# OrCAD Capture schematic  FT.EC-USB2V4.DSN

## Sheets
1 INDEX: title: 01- INDEX; rev: 1.0; note: 17 HaYetsira Street; note: Yokneam Illit, Israel 2069208
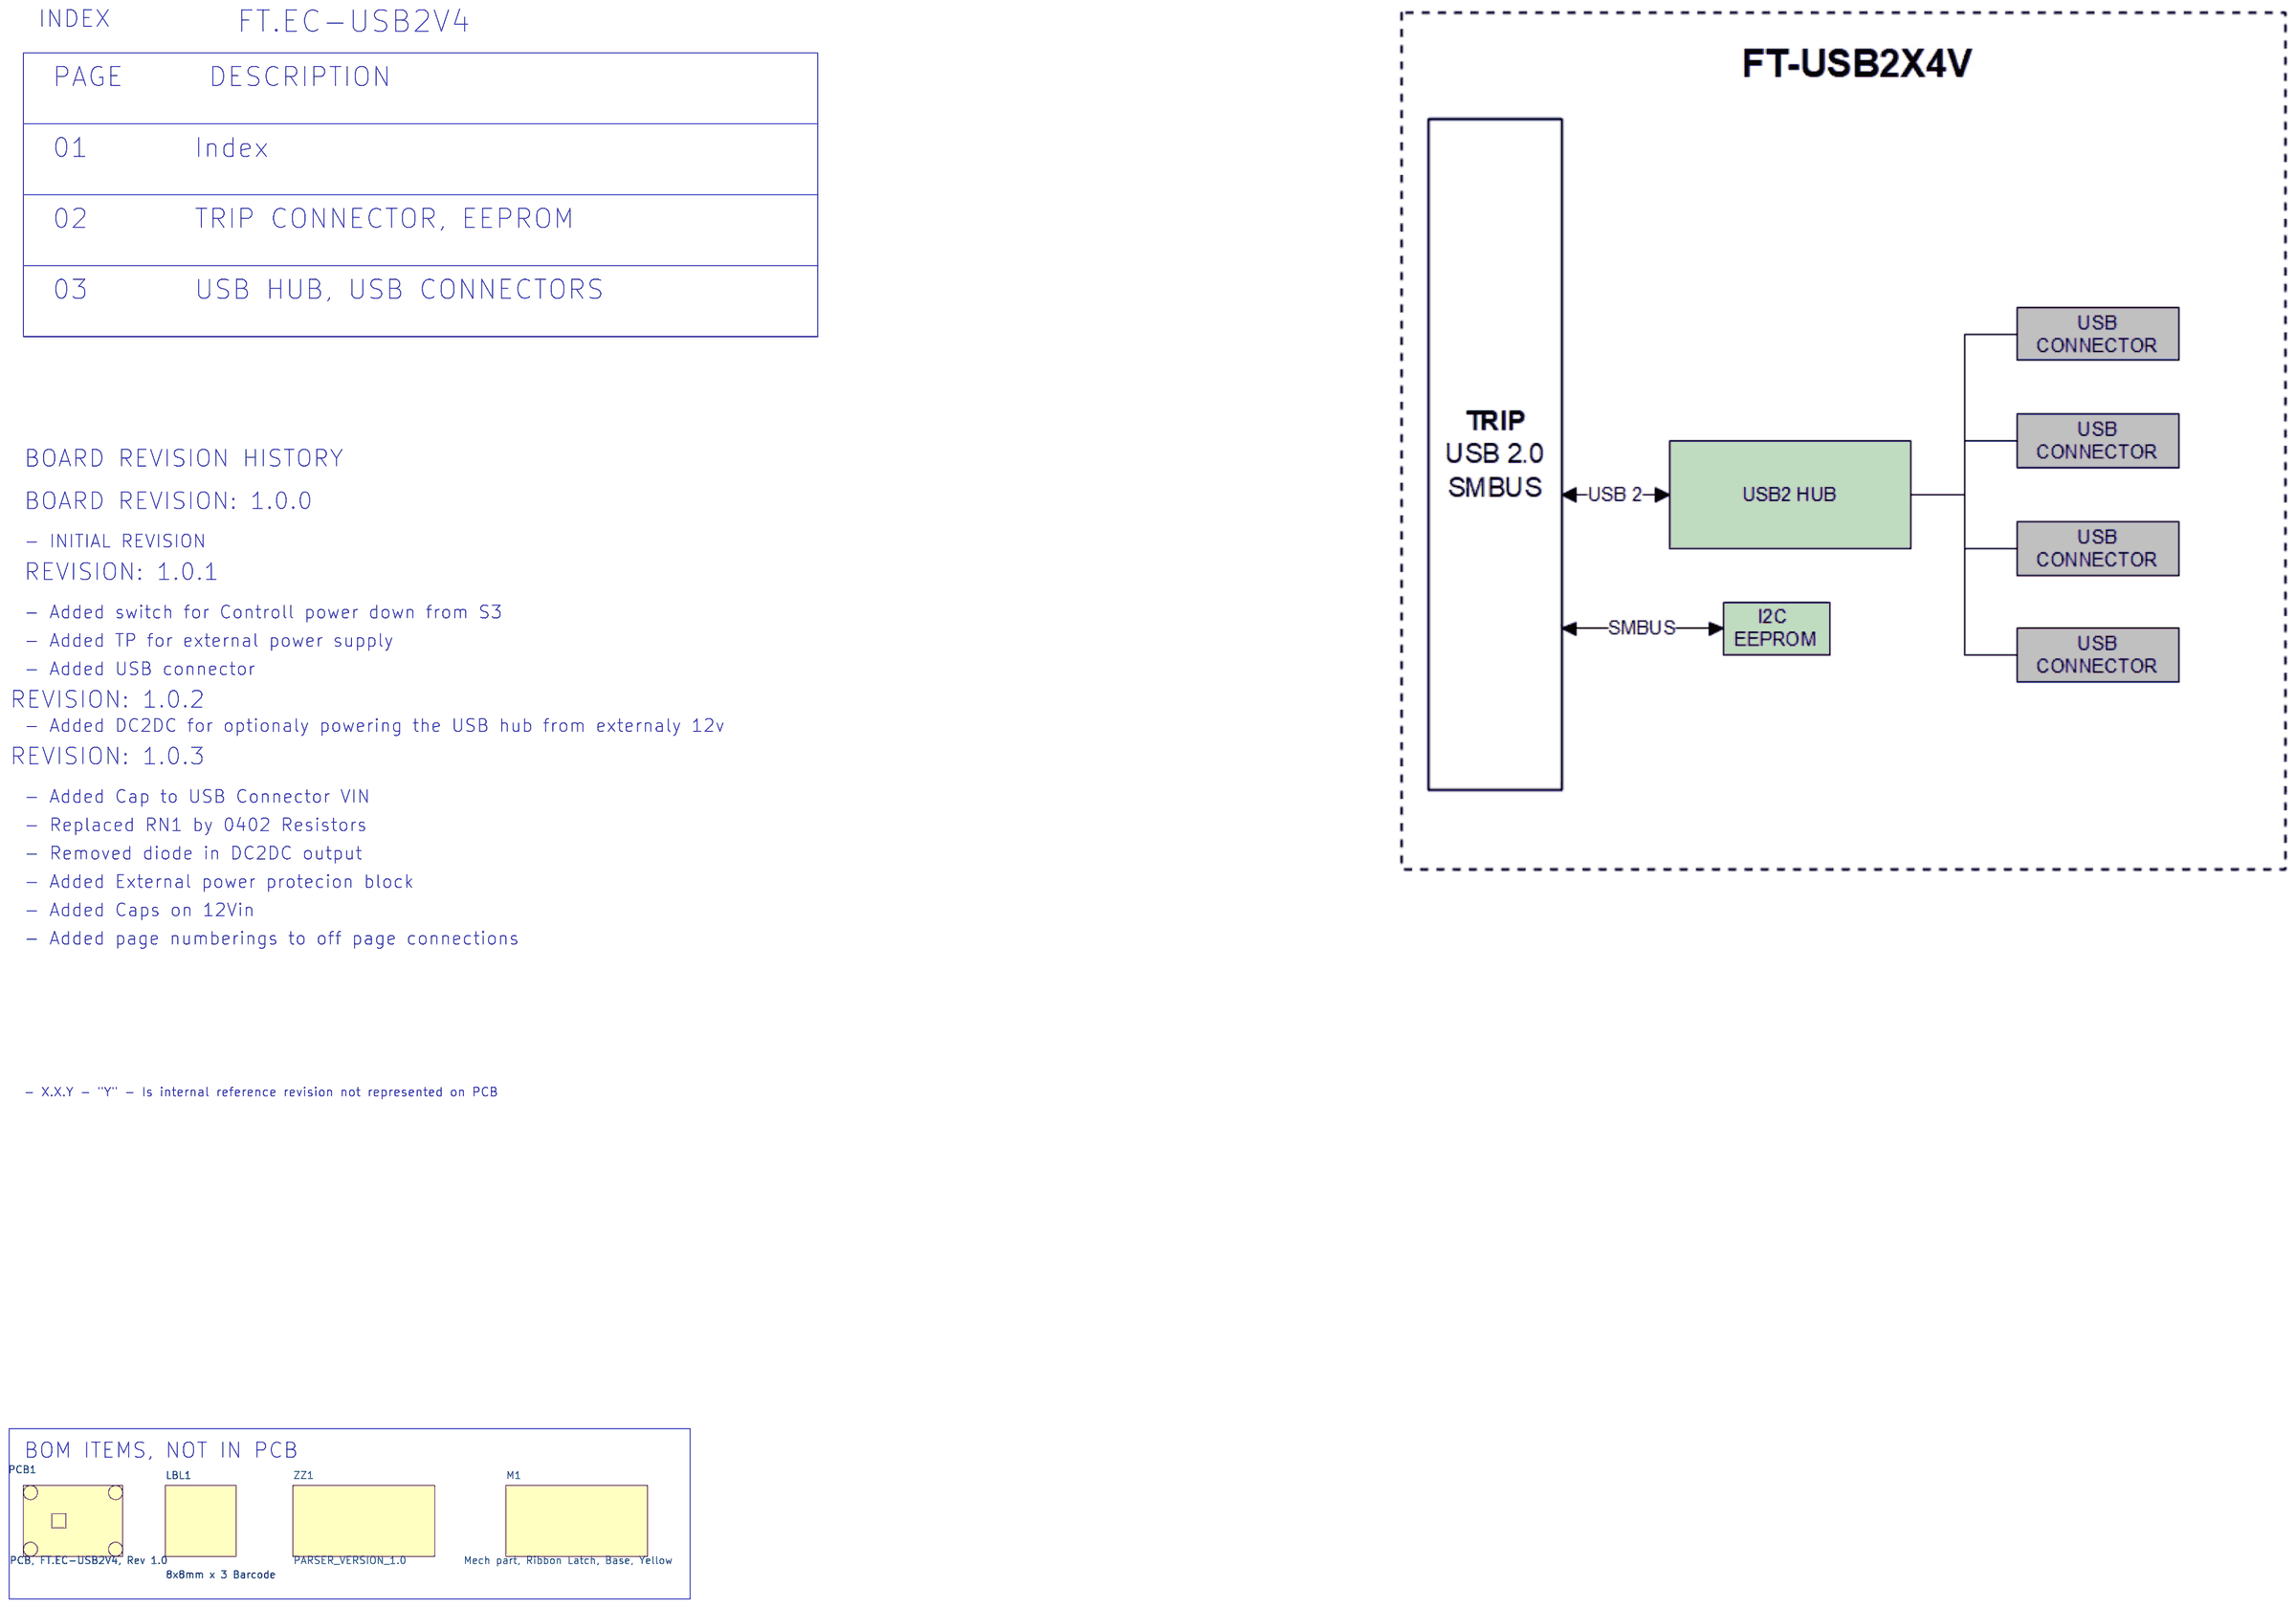
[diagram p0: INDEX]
2 CONN: size A3; title: 02- connector
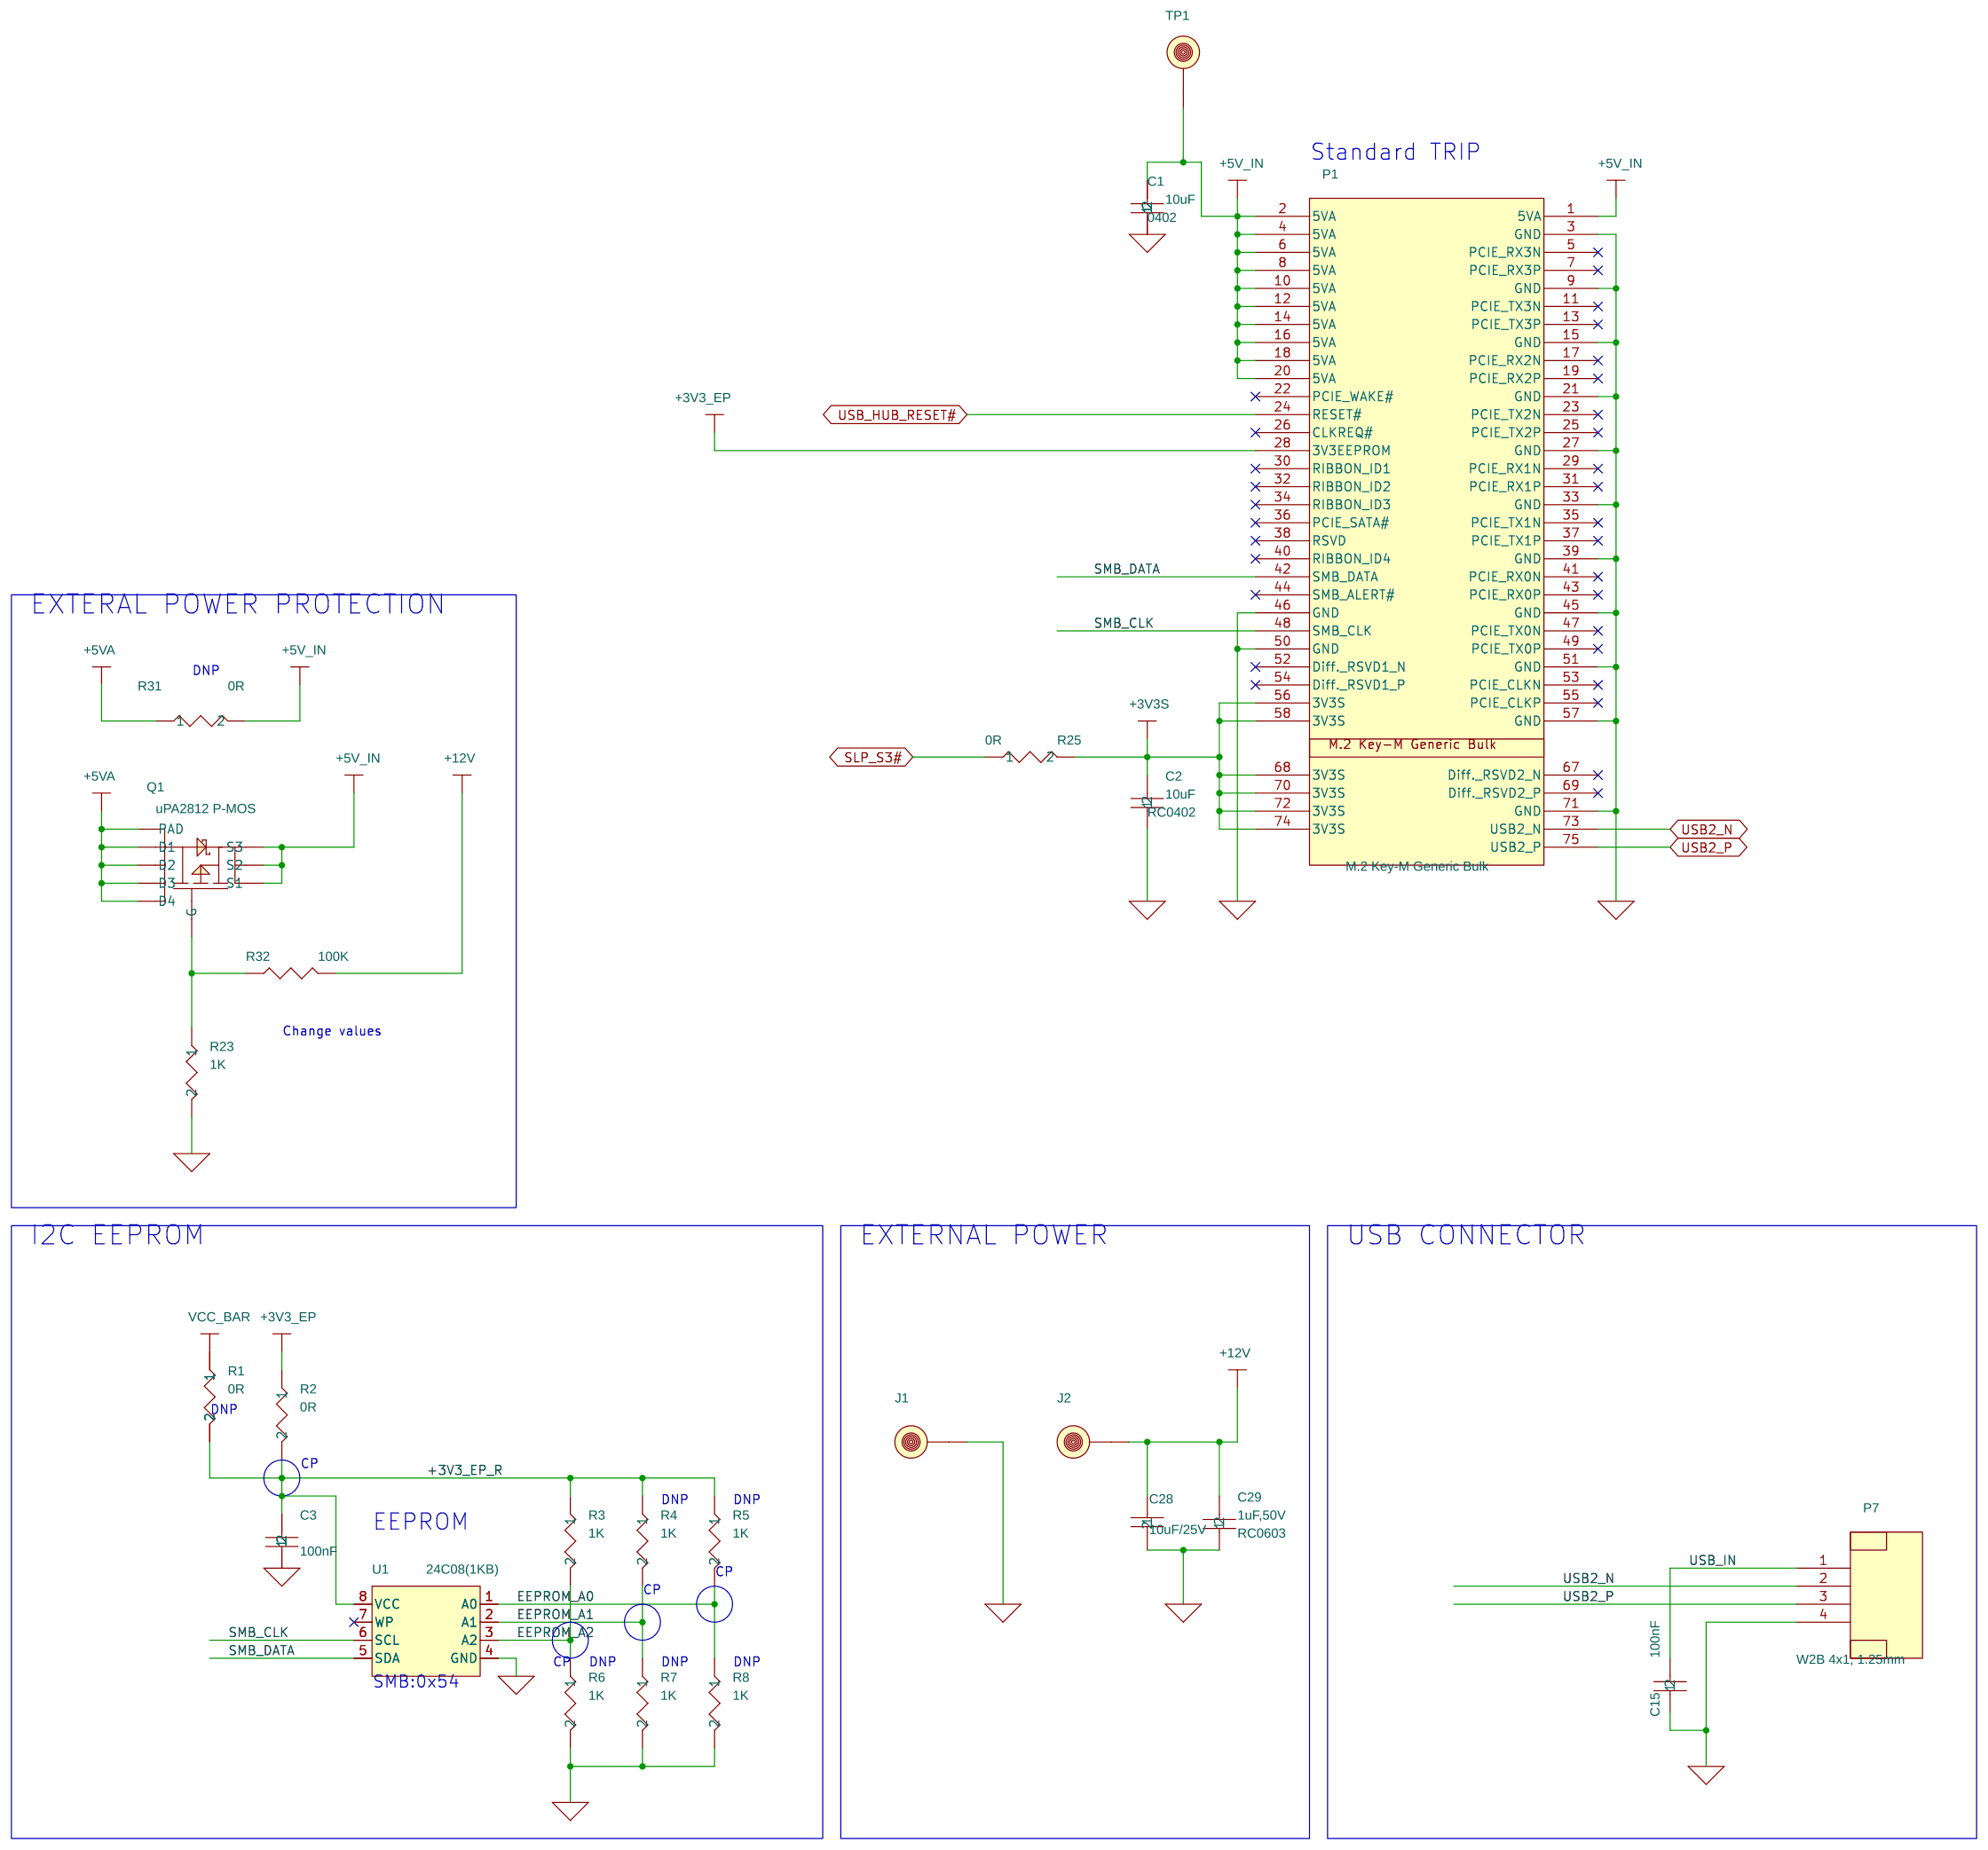
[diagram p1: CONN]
3 HUB, CONN: size A3; title: 03- HUB, USB CONN
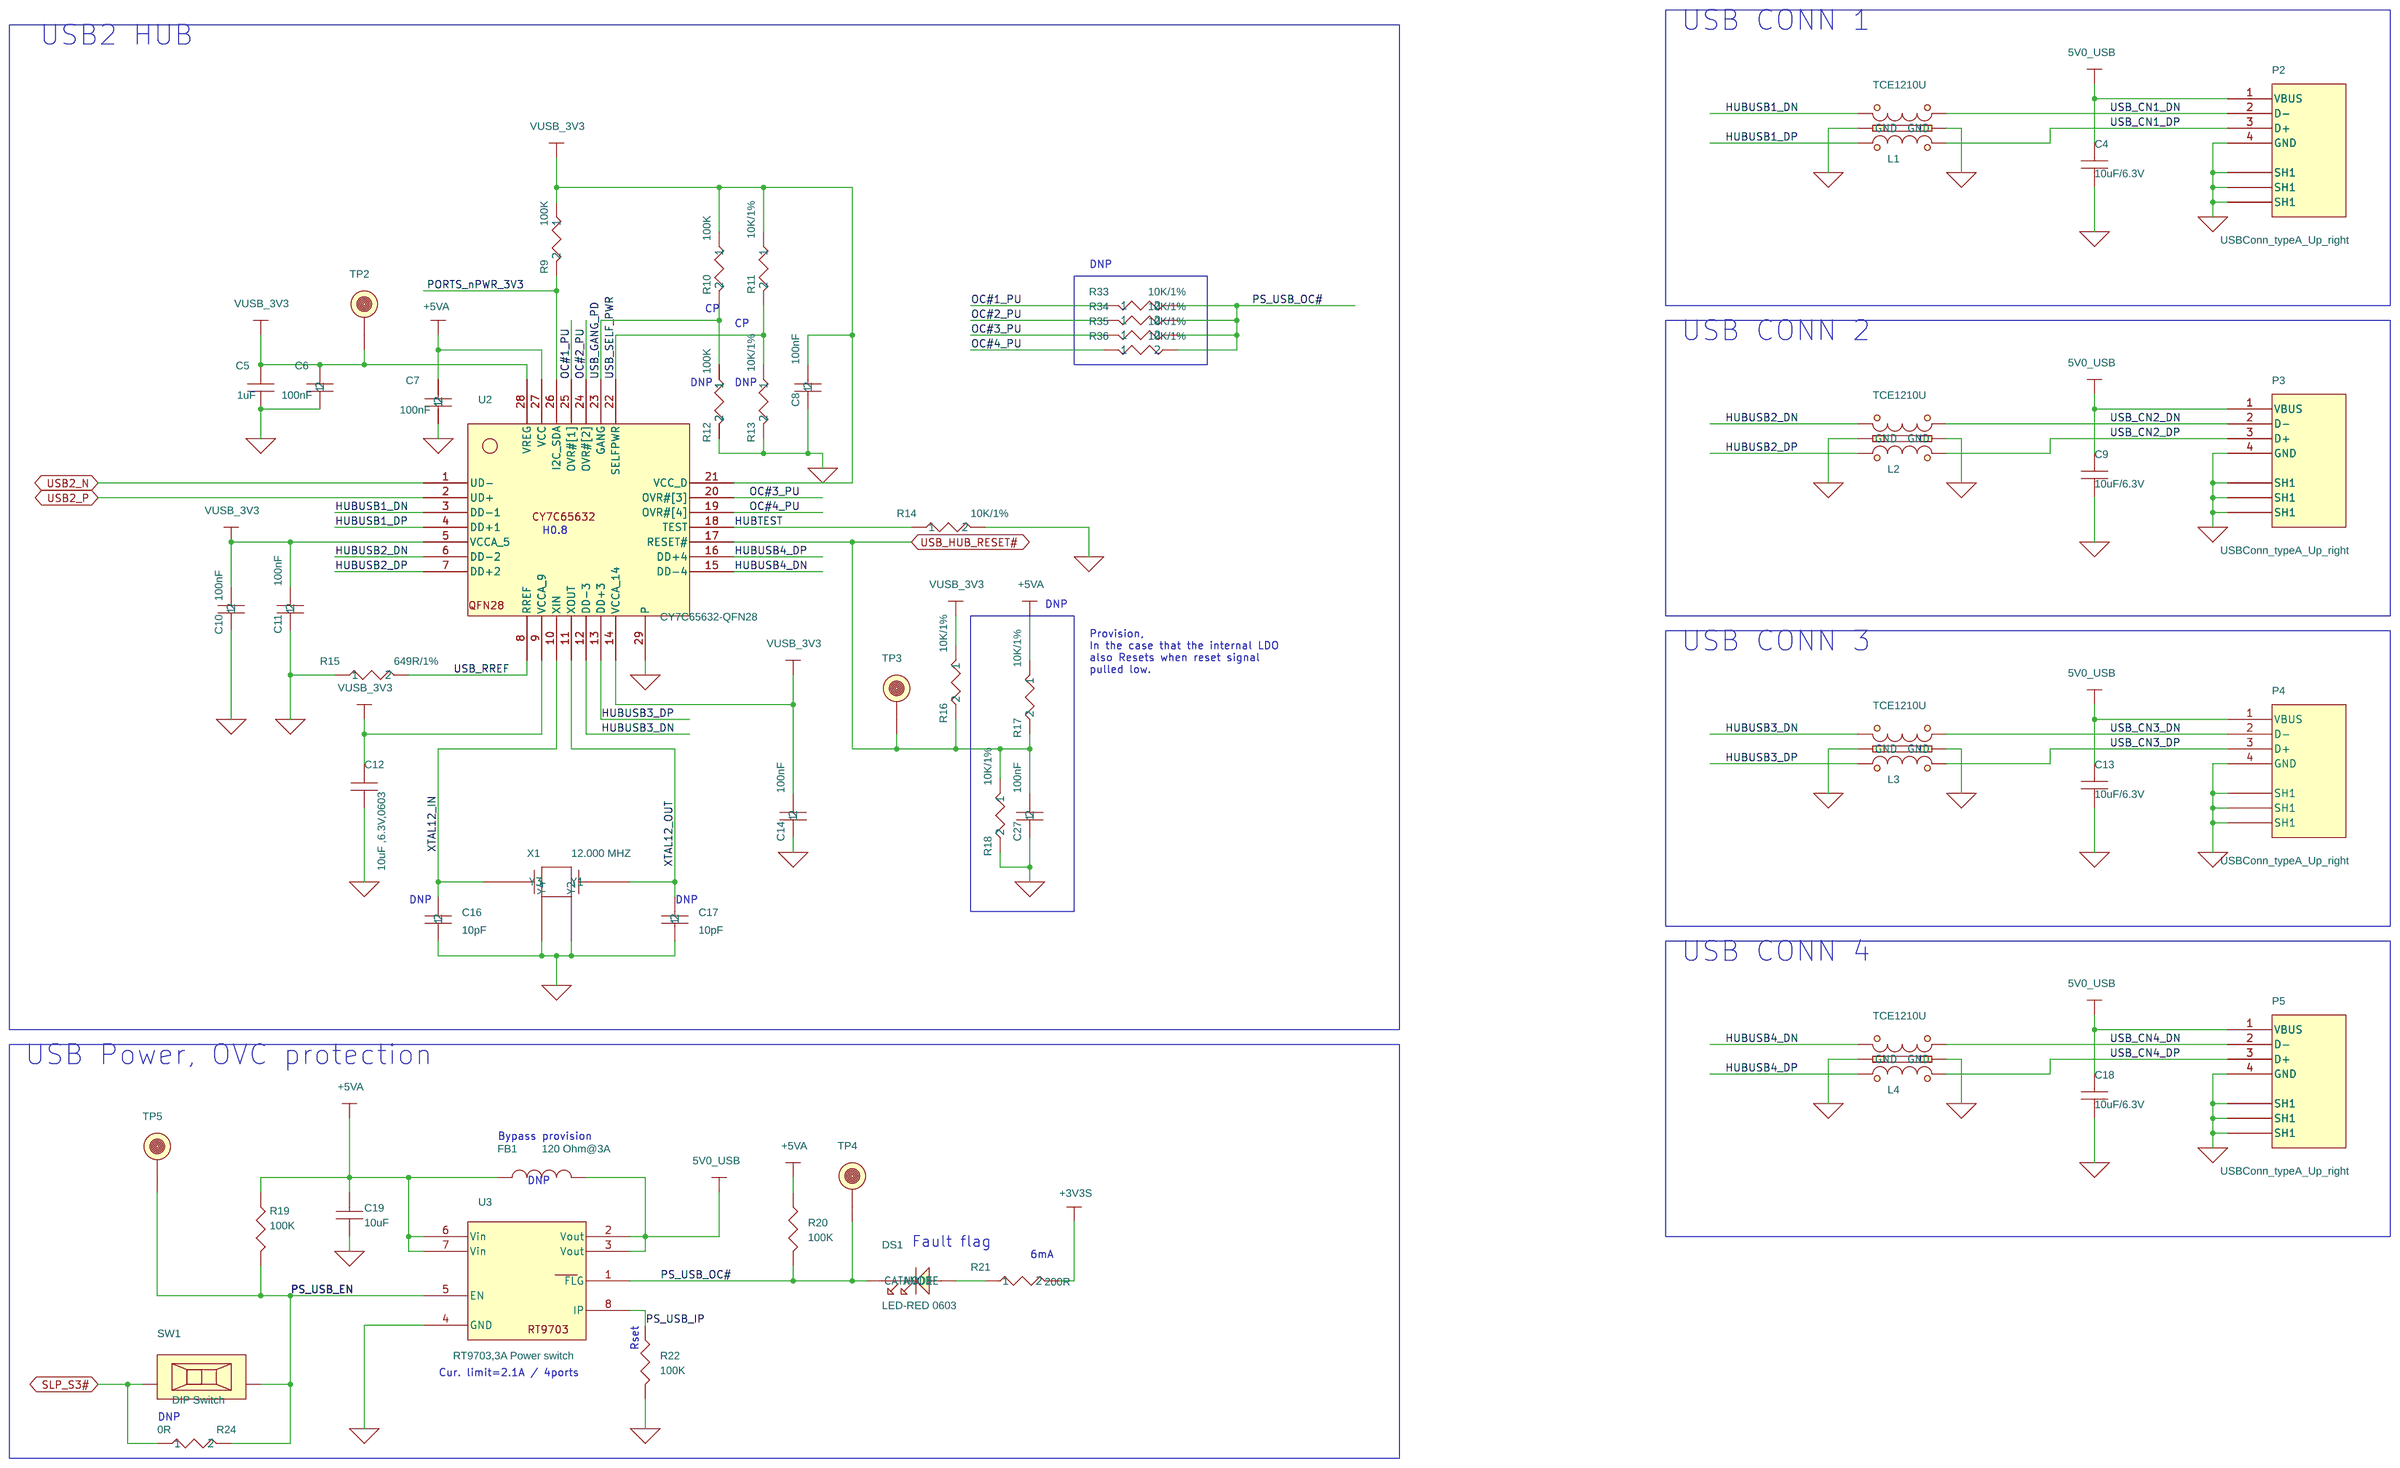
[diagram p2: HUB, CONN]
4 POWER: size A3; title: 04-POWER
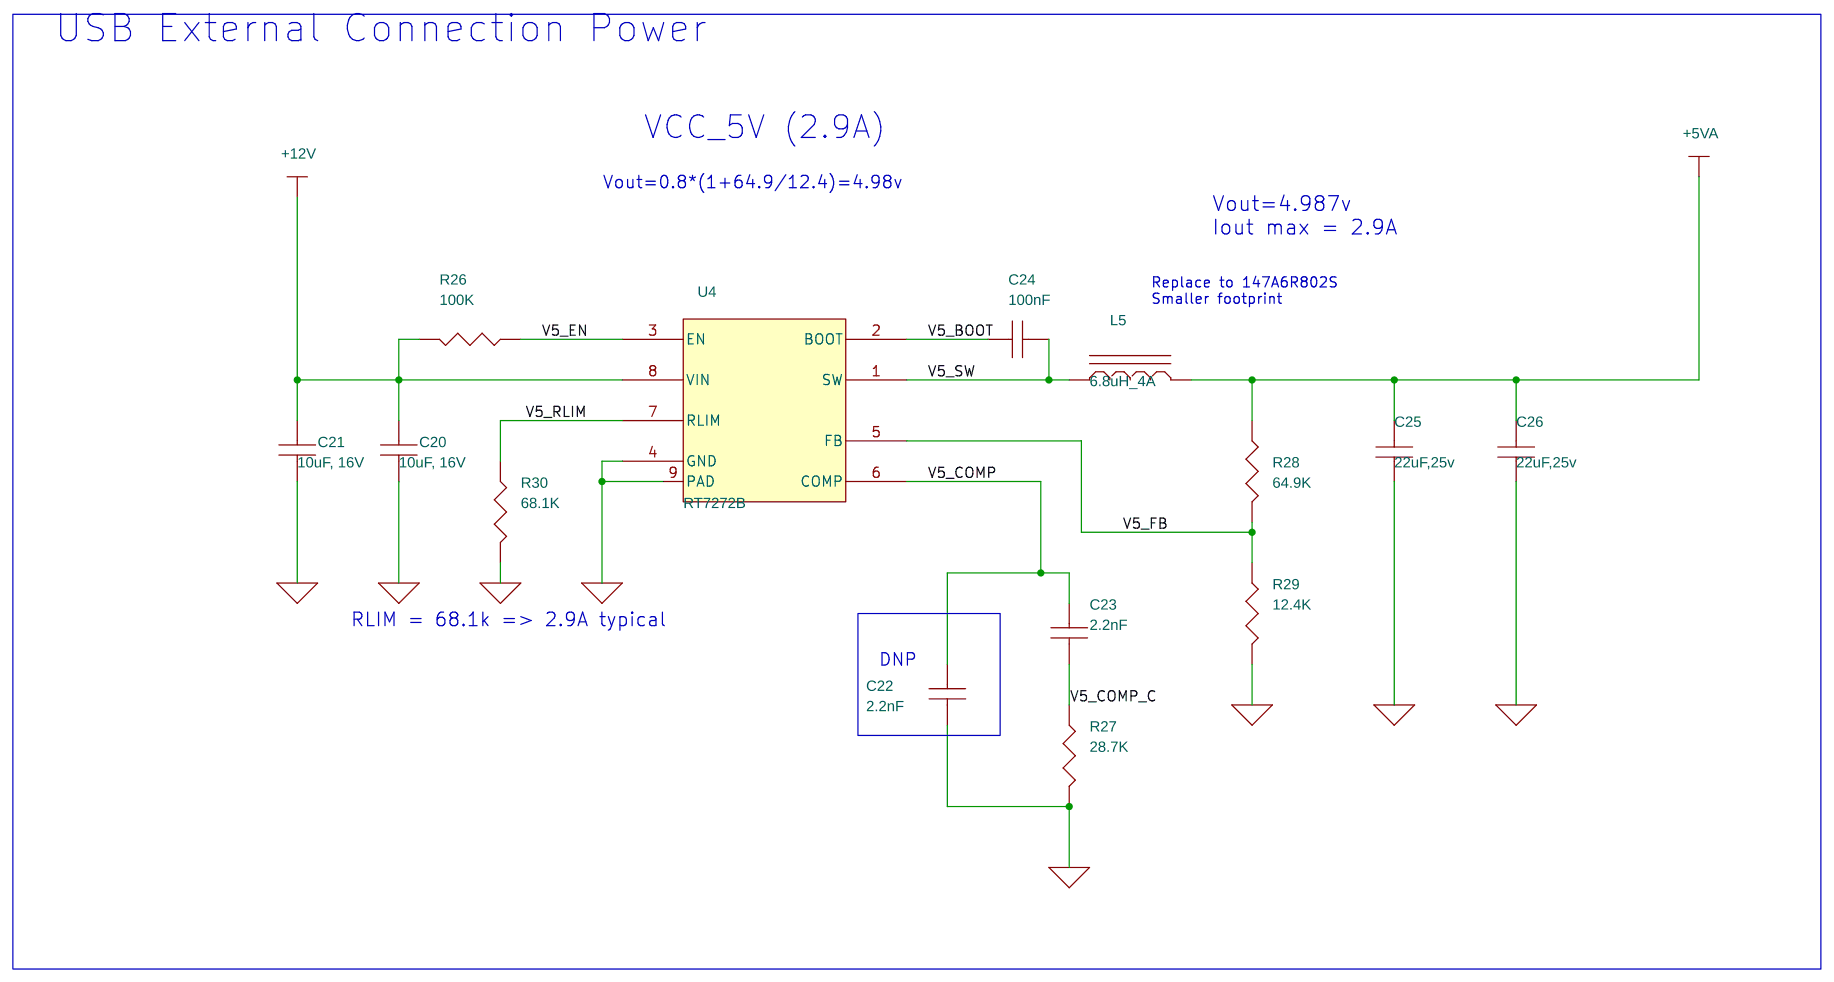
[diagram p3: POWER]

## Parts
sheet CONN
C1  10uF  [0402]
C2  10uF  [RC0402]
C3  100nF  [RC0402]
C15  100nF  [RC0402]
C28  10uF/25V  [0603]
C29  1uF,50V  [RC0603]
J1  TPRTH1_5m  [TPRTH1_5m]
J2  TPRTH1_5m  [TPRTH1_5m]
P1  M.2 Key-M Generic Bulk  [NGFF67P8HMkeySM]
P7  W2B 4x1, 1.25mm  [1x4W2B1_25RASM]
Q1  uPA2812 P-MOS  [Powerpak1212-8]
R1  0R  [RC0402]
R2  0R  [RC0402]
R3  1K  [RC0402]
R4  1K  [RC0402]
R5  1K  [RC0402]
R6  1K  [RC0402]
R7  1K  [RC0402]
R8  1K  [RC0402]
R23  1K  [RC0402]
R25  0R  [RC0402]
R31  0R  [RC0402]
R32  100K  [RC0402]
TP1  TP
U1  24C08(1KB)  [MO-229VCED-2]
sheet HUB, CONN
C4  10uF/6.3V  [RC0603]
C5  1uF  [RC0402]
C6  100nF  [RC0402]
C7  100nF  [RC0402]
C8  100nF  [RC0402]
C9  10uF/6.3V  [RC0603]
C10  100nF  [RC0402]
C11  100nF  [RC0402]
C12  10uF ,6.3V,0603  [RC0603]
C13  10uF/6.3V  [RC0603]
C14  100nF  [RC0402]
C16  10pF  [RC0402]
C17  10pF  [RC0402]
C18  10uF/6.3V  [RC0603]
C19  10uF  [C0603-08]
C27  100nF  [RC0402]
DS1  LED-RED 0603  [LED-0603]
FB1  120 Ohm@3A  [FB1206]
L1  TCE1210U  [EMI1012-ESD]
L2  TCE1210U  [EMI1012-ESD]
L3  TCE1210U  [EMI1012-ESD]
L4  TCE1210U  [EMI1012-ESD]
P2  USBConn_typeA_Up_right  [USB-A-UP-TH]
P3  USBConn_typeA_Up_right  [USB-A-UP-TH]
P4  USBConn_typeA_Up_right  [USB-A-UP-TH]
P5  USBConn_typeA_Up_right  [USB-A-UP-TH]
R9  100K  [RC0402]
R10  100K  [RC0402]
R11  10K/1%  [RC0402]
R12  100K  [RC0402]
R13  10K/1%  [RC0402]
R14  10K/1%  [RC0402]
R15  649R/1%  [RC0402]
R16  10K/1%  [RC0402]
R17  10K/1%  [RC0402]
R18  10K/1%  [RC0402]
R19  100K  [RC0402]
R20  100K  [RC0402]
R21  200R  [RC0402]
R22  100K  [RC0402]
R24  0R  [RC0402]
R33  10K/1%  [RC0402]
R34  10K/1%  [RC0402]
R35  10K/1%  [RC0402]
R36  10K/1%  [RC0402]
SW1  DIP Switch  [SWDIP-1SM]
TP2  TP
TP3  TP
TP4  TP
TP5  TP
U2  CY7C65632-QFN28  [QFN28]
U3  RT9703,3A Power switch  [SO-8-150]
X1  12.000 MHZ  [OSC3225]
sheet INDEX
LBL1  8x8mm x 3 Barcode  [LBL XYU]
M1  Mech part, Ribbon Latch, Base, Yellow
PCB1  PCB, FT.EC-USB2V4, Rev 1.0
ZZ1  PARSER_VERSION_1.0
sheet POWER
C20  10uF, 16V  [RC0603]
C21  10uF, 16V  [RC0603]
C22  2.2nF  [RC0402]
C23  2.2nF  [RC0402]
C24  100nF  [RC0402]
C25  22uF,25v  [C0805]
C26  22uF,25v  [C0805]
L5  6.8uH_4A  [IND6x5_5x3]
R26  100K  [RC0402]
R27  28.7K  [RC0402]
R28  64.9K  [RC0402]
R29  12.4K  [RC0402]
R30  68.1K  [RC0402]
U4  RT7272B  [PSOP-8-2X2]

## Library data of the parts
C1 = 100nF,_10V,_X7R,_10%,_0402_2: CLABCONF0: =USB2X4; P/N: 151B10600S
C2 = 100nF,_10V,_X7R,_10%,_0402_1: CLABCONF0: =USB2X4; P/N: 151B10600S
C3 = 15pF,_50V,_NPO,_5%,_0402: CLABCONF0: =USB2X4; P/N: 151B10400S
C6 C15 = 100nF,_10V,_X7R,_10%,_0402_3: CLABCONF0: =USB2X4
C28 = 10uF_25V_X5R_X7R_20%_0603: CLABCONF0: =SBC-APL
C29 = 100nF,_10V,_X7R,_10%,_0402: CLABCONF0: =SBC-ATCFL; P/N: 151D10510S
J1 = TP_SMT_2: CLABCONF0: =DNP; P/N: 188Z01390
J2 = TP_SMT_1: CLABCONF0: =DNP; P/N: 188Z01390
P1 = M.2_Key-M_Generic_Bulk: CLABCONF0: =USB2X4; P/N: 182K06700S
P7 = W2B_4x1_HDR,_1.25mm: CLABCONF0: =USB; P/N: 182E00401S
Q1 = FDMC510P_-_P-MOS_1: CLABCONF0: =USB2X4; P/N: 131D10060S
R1 = 348R,1%,0402,1_16W_3: CLABCONF0: =DNP; P/N: 161C00005S
R2 = 348R,1%,0402,1_16W_7: CLABCONF0: =USB2X4; P/N: 161C00005S
R3 = 348R,1%,0402,1_16W_5: CLABCONF0: =USB2X4; P/N: 161C10011S
R4 = 348R,1%,0402,1_16W_1: CLABCONF0: =DNP; P/N: 161C10011S
R5 = 348R,1%,0402,1_16W_2: CLABCONF0: =DNP; P/N: 161C10011S
R6 = 348R,1%,0402,1_16W: CLABCONF0: =DNP; P/N: 161C10011S
R7 = 348R,1%,0402,1_16W_6: CLABCONF0: =DNP; P/N: 161C10011S
R8 = 348R,1%,0402,1_16W_4: CLABCONF0: =DNP; P/N: 161C10011S
R23 = 348R,1%,0402,1_16W_9: CLABCONF0: =USB2X4; P/N: 161C10011S
R24 R25 = 0R: CLABCONF0: =DNP
R31 = 348R,1%,0402,1_16W_8: CLABCONF0: =DNP; P/N: 161C00005S
R19 R20 R22 R26 R32 = 100K,_0402_0: CLABCONF0: =USB2X4
TP1-TP5 = TP_SMT: CLABCONF0: =DNP
U1 = 24C02,_serial_EE,_2KB,_I2C: CLABCONF0: =USB2X4; P/N: 111S31000S
C4 C9 C13 C18 = 10uF,6.3V,0603,20%X5R: CLABCONF0: =USB2X4; P/N: 151B10610S
C5 = Cap_1uF,X5R,6.3V,0402: CLABCONF0: =USB2X4
C7 = 100nF,_10V,_X7R,_10%,_0402_4: CLABCONF0: =USB2X4; Group: LAN2
C8 = 100nF,_10V,_X7R,_10%,_0402_1: CLABCONF0: =USB2X4
C10 = 100nF,_10V,_X7R,_10%,_0402_5: CLABCONF0: =USB2X4
C11 = 100nF,_10V,_X7R,_10%,_0402_6: CLABCONF0: =USB2X4
C12 = 10uF,6.3V,0603,X5R: CLABCONF0: =USB2X4
C14 = 100nF,_10V,_X7R,_10%,_0402: CLABCONF0: =USB2X4
C16 = 10pF,50V,NPO,_5%,_0402_1: CLABCONF0: =DNP
C17 = 10pF,50V,NPO,_5%,_0402: CLABCONF0: =DNP
C19 = 10uF,6.3V,0603,20%,X5R_0: CLABCONF0: =USB2X4
C27 = 100nF,_10V,_X7R,_10%,_0402_2: CLABCONF0: =USB2X4
DS1 = LED-RED_0603: CLABCONF0: =USB2X4
FB1 = Ferrite_bead_,_120_Ohm@3A: CLABCONF0: =DNP
L1-L4 = ESD_CHOKE_DIFFx2_10: CLABCONF0: =USB2X4; P/N: 142D11801S
P2 = USB_Type_A_Upright_1_2: CLABCONF0: =USB2X4
P3 = USB_Type_A_Upright_1: CLABCONF0: =USB2X4
P4 = USB_Type_A_Upright_1_1: CLABCONF0: =USB2X4
P5 = USB_Type_A_Upright_1_3: CLABCONF0: =USB2X4
R9 = 100K,_0402_1: CLABCONF0: =USB2X4; P/N: 161C10031S
R10 = 100K,_0402: CLABCONF0: =USB2X4; P/N: 161C10031S
R11 = 10K,1%,0402,1_16W_4: CLABCONF0: =USB2X4
R12 = 100K,_0402_2: CLABCONF0: =DNP; P/N: 161C10031S
R13 = 10K,1%,0402,1_16W_5: CLABCONF0: =DNP
R14 = 10K,1%,0402,1_16W_2: CLABCONF0: =USB2X4
R15 = 649R,1%,0402,1_16W: CLABCONF0: =USB2X4
R16 = 10K,1%,0402,1_16W_1: CLABCONF0: =USB2X4
R17 = 10K,1%,0402,1_16W_9: CLABCONF0: =DNP
R18 = 10K,1%,0402,1_16W_6: CLABCONF0: =DNP
R21 = 0R_1: CLABCONF0: =USB2X4; P/N: 161C20001S
R33 = 10K,1%,0402,1_16W_3: CLABCONF0: =DNP
R34 = 10K,1%,0402,1_16W: CLABCONF0: =DNP
R35 = 10K,1%,0402,1_16W_8: CLABCONF0: =DNP
R36 = 10K,1%,0402,1_16W_7: CLABCONF0: =DNP
SW1 = SW_DIP_Switch_x1: CLABCONF0: =USB2X4; P/N: 170I30100S
U2 = TMP_0: CLABCONF0: =USB2X4
U3 = RT9703,3A_Power_switch+FLG: CLABCONF0: =USB2X4
X1 = TMP_1: CLABCONF0: =USB2X4; P/N: 141B12604I
LBL1 = Label_8x8mm_x_3_for_Barcode: CLABCONF0: =USB2X4
M1 = PARSER_VERSION_1_0.0: CLABCONF0: =USB2X4; P/N: 290E010010
PCB1 = SBC-iHSW_Rev_1.0: CLABCONF0: =USB2X4; P/N: 188C03640U
ZZ1 = PARSER_VERSION_1.0: CLABCONF0: =USB2X4
C20 C21 = 22uF_25V: CLABCONF0: =USB2X4; P/N: 151C10610S
C22 = 2_0.2nF,_50V,_X7R,_10%,_0402: CLABCONF0: =DNP
C23 = 2.2nF,_50V,_X7R,_10%,_0402: CLABCONF0: =USB2X4
C24 = 100nF,_10V,_X7R,_10%,_0402_0: CLABCONF0: =USB2X4; Group: LAN2
C25 C26 = 100nF,_10V,_X7R,_10%,_0402_0: CLABCONF0: =USB2X4; P/N: 151C22620S
L5 = IND_6.8uH_3.5A: CLABCONF0: =USB2X4; P/N: 147A6R802S
R27 = 40.2k_1%: CLABCONF0: =USB2X4; P/N: 161C28721S
R28 = 10.5K_1%,0402: CLABCONF0: =USB2X4; P/N: 161C64921S
R29 = 2.37K_1%,_0402: CLABCONF0: =USB2X4; P/N: 161C12421S
R30 = 2.37K_1%,_0402: CLABCONF0: =USB2X4; P/N: 161C68121S
U4 = RT7272B,Converter,3A,36V: CLABCONF0: =USB2X4; P/N: 123V30000S

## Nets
5V0_USB: C4.1 C9.1 C13.1 C18.1 FB1.2 P2.1(VBUS) P3.1(VBUS) P4.1(VBUS) P5.1(VBUS) U3.2(Vout) U3.3(Vout)
+3V3_EP: P1.28(3V3EEPROM) R2.1
+3V3_EP_R: C3.2 R1.2 R2.2 R3.1 R4.1 R5.1 U1.8(VCC)
+3V3S: C2.2 P1.56(3V3S) P1.58(3V3S) P1.68(3V3S) P1.70(3V3S) P1.72(3V3S) P1.74(3V3S) R1.1 R21.2 R25.2
+5V_IN: C1.2 P1.1(5VA) P1.2(5VA) P1.4(5VA) P1.6(5VA) P1.8(5VA) P1.10(5VA) P1.12(5VA) P1.14(5VA) P1.16(5VA) P1.18(5VA) P1.20(5VA) Q1.1(S1) Q1.2(S2) Q1.3(S3) R31.2 TP1.1
+5VA: C7.2 C19.2 C25.2 C26.2 FB1.1 L5.2 Q1.5(D1) Q1.6(D2) Q1.7(D3) Q1.8(D4) Q1.9(PAD) R17.1 R19.1 R20.1 R28.1 R31.1 U2.27(VCC) U3.6(Vin) U3.7(Vin)
+12V: C20.1 C21.1 C28.1 C29.2 J2.1 R26.2 R32.2 U4.8(VIN)
GND: C1.1 C2.1 C3.1 C4.2 C5.1 C6.1 C7.1 C8.1 C9.2 C10.1 C11.1 C12.1 C13.2 C14.1 C15.1 C16.1 C17.1 C18.2 C19.1 C20.2 C21.2 C22.2 C25.1 C26.1 C27.1 C28.2 C29.1 J1.1 L1.5(GND) L1.6(GND) L2.5(GND) L2.6(GND) L3.5(GND) L3.6(GND) L4.5(GND) L4.6(GND) P1.3(GND) P1.9(GND) P1.15(GND) P1.21(GND) P1.27(GND) P1.33(GND) P1.39(GND) P1.45(GND) P1.46(GND) P1.50(GND) P1.51(GND) P1.57(GND) P1.71(GND) P2.4(GND) P2.SH1 P3.4(GND) P3.SH1 P4.4(GND) P4.SH1 P5.4(GND) P5.SH1 P7.4 R6.2 R7.2 R8.2 R12.2 R13.2 R14.2 R15.1 R18.2 R22.2 R23.2 R27.2 R29.2 R30.2 U1.4(GND) U2.29(P) U3.4(GND) U4.4(GND) U4.9(PAD) X1.2(Y2) X1.4(Y4)
V5_BOOT: C24.1 U4.2(BOOT)
V5_COMP: C22.1 C23.1 U4.6(COMP)
V5_COMP_C: C23.2 R27.1
V5_EN: R26.1 U4.3(EN)
V5_FB: R28.2 R29.1 U4.5(FB)
V5_RLIM: R30.1 U4.7(RLIM)
V5_SW: C24.2 L5.1 U4.1(SW)
EEPROM_A0: R5.2 R8.1 U1.1(A0)
EEPROM_A1: R4.2 R7.1 U1.2(A1)
EEPROM_A2: R3.2 R6.1 U1.3(A2)
HUBTEST: R14.1 U2.18(TEST)
HUBUSB1_DN: L1.3 U2.3(DD-1)
HUBUSB1_DP: L1.4 U2.4(DD+1)
HUBUSB2_DN: L2.3 U2.6(DD-2)
HUBUSB2_DP: L2.4 U2.7(DD+2)
HUBUSB3_DN: L3.3 U2.12(DD-3)
HUBUSB3_DP: L3.4 U2.13(DD+3)
HUBUSB4_DN: L4.3 U2.15(DD-4)
HUBUSB4_DP: L4.4 U2.16(DD+4)
OC#1_PU: R33.1 U2.25(OVR#[1])
OC#2_PU: R34.1 U2.24(OVR#[2])
OC#3_PU: R35.1 U2.20(OVR#[3])
OC#4_PU: R36.1 U2.19(OVR#[4])
PORTS_nPWR_3V3: R9.2 U2.26(I2C_SDA)
PS_USB_EN: R19.2 R24.2 SW1.2 TP5.1 U3.5(EN)
PS_USB_IP: R22.1 U3.8(IP)
PS_USB_OC#: DS1.CATHODE R20.2 R33.2 R34.2 R35.2 R36.2 TP4.1 U3.1(FLG)
SLP_S3#: R24.1 R25.1 SW1.1
SMB_CLK: P1.48(SMB_CLK) U1.6(SCL)
SMB_DATA: P1.42(SMB_DATA) U1.5(SDA)
USB2_N: P1.73(USB2_N) P7.2 U2.1(UD-)
USB2_P: P1.75(USB2_P) P7.3 U2.2(UD+)
USB_CN1_DN: L1.2 P2.2(D-)
USB_CN1_DP: L1.1 P2.3(D+)
USB_CN2_DN: L2.2 P3.2(D-)
USB_CN2_DP: L2.1 P3.3(D+)
USB_CN3_DN: L3.2 P4.2(D-)
USB_CN3_DP: L3.1 P4.3(D+)
USB_CN4_DN: L4.2 P5.2(D-)
USB_CN4_DP: L4.1 P5.3(D+)
USB_GANG_PD: R10.2 R12.1 U2.23(GANG)
USB_HUB_RESET#: C27.2 P1.24(RESET#) R16.2 R17.2 R18.1 TP3.1 U2.17(RESET#)
USB_IN: C15.2 P7.1
USB_RREF: R15.2 U2.8(RREF)
USB_SELF_PWR: R11.2 R13.1 U2.22(SELFPWR)
VUSB_3V3: C5.2 C6.2 C8.2 C10.2 C11.2 C12.2 C14.2 R9.1 R10.1 R11.1 R16.1 TP2.1 U2.5(VCCA) U2.9(VCCA) U2.14(VCCA) U2.21(VCC_D) U2.28(VREG)
XTAL12_IN: C16.2 U2.10(XIN) X1.3(Y3)
XTAL12_OUT: C17.2 U2.11(XOUT) X1.1(Y1)
N16845801: DS1.ANODE R21.1
N16868025: Q1.4(G) R23.1 R32.1

Not connected (* = marked no-connect by the designer): P1 5(PCIE_RX3N)* 7(PCIE_RX3P)* 11(PCIE_TX3N)* 13(PCIE_TX3P)* 17(PCIE_RX2N)* 19(PCIE_RX2P)* 22(PCIE_WAKE#)* 23(PCIE_TX2N)* 25(PCIE_TX2P)* 26(CLKREQ#)* 29(PCIE_RX1N)* 30(RIBBON_ID1)* 31(PCIE_RX1P)* 32(RIBBON_ID2)* 34(RIBBON_ID3)* 35(PCIE_TX1N)* 36(PCIE_SATA#)* 37(PCIE_TX1P)* 38(RSVD)* 40(RIBBON_ID4)* 41(PCIE_RX0N)* 43(PCIE_RX0P)* 44(SMB_ALERT#)* 47(PCIE_TX0N)* 49(PCIE_TX0P)* 52(Diff._RSVD1_N)* 53(PCIE_CLKN)* 54(Diff._RSVD1_P)* 55(PCIE_CLKP)* 67(Diff._RSVD2_N)* 69(Diff._RSVD2_P)*; U1 7(WP)*

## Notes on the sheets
sheet 1
- INDEX
- FT.EC-USB2V4
- PAGE
- DESCRIPTION
- 01
- Index
- 02
- TRIP CONNECTOR, EEPROM
- 03
- USB HUB, USB CONNECTORS
- BOARD REVISION HISTORY
- BOARD REVISION: 1.0.0
- - INITIAL REVISION
- REVISION: 1.0.1
- - Added switch for Controll power down from S3
- - Added TP for external power supply
- - Added USB connector
- REVISION: 1.0.2
- - Added DC2DC for optionaly powering the USB hub from externaly 12v
- REVISION: 1.0.3
- - Added Cap to USB Connector VIN
- - Replaced RN1 by 0402 Resistors
- - Removed diode in DC2DC output
- - Added External power protecion block
- - Added Caps on 12Vin
- - Added page numberings to off page connections
- - X.X.Y - "Y" - Is internal reference revision not represented on PCB
- BOM ITEMS, NOT IN PCB
sheet 2
- Standard TRIP
- EXTERAL POWER PROTECTION
- DNP
- Change values
- I2C EEPROM
- EXTERNAL POWER
- USB CONNECTOR
- DNP
- CP
- DNP
- DNP
- EEPROM
- CP
- CP
- CP
- DNP
- DNP
- DNP
- SMB:0x54
sheet 3
- USB CONN 1
- USB2 HUB
- DNP
- CP
- CP
- USB CONN 2
- DNP
- DNP
- H0.8
- DNP
- Provision,
  In the case that the internal LDO
  also Resets when reset signal
  pulled low.
- USB CONN 3
- DNP
- DNP
- USB CONN 4
- USB Power, OVC protection
- Bypass provision
- DNP
- Fault flag
- 6mA
- Rset
- Cur. limit=2.1A / 4ports
- DNP
sheet 4
- USB External Connection Power
- VCC_5V (2.9A)
- Vout=0.8*(1+64.9/12.4)=4.98v
- Vout=4.987v
  Iout max = 2.9A
- Replace to 147A6R802S
  Smaller footprint
- RLIM = 68.1k => 2.9A typical
- DNP
